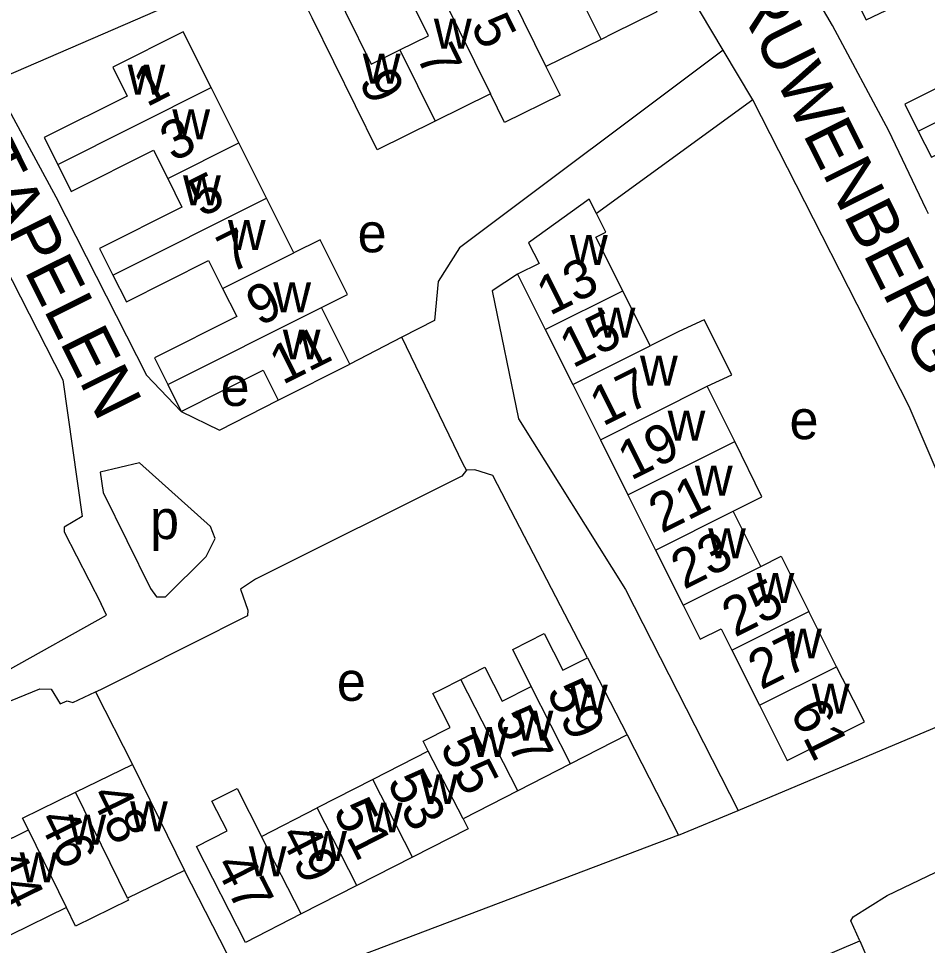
# Model space of a CAD drawing. Extents: x 157794 to 159375, y 380877 to 382306.
# Drawn here: x 158508.3 to 158601.4, y 381608 to 381703 of the extents above; entities that cross this region are included whole.
import ezdxf

# ---------------------------------------------------------------- set-up
doc = ezdxf.new("R2010")
doc.units = 0
for name, color, linetype in [('BLT_Basislijn', 7, 'Continuous'), ('BLT_Bebouwing', 7, 'Continuous'), ('BLT_Centroide', 7, 'Continuous'), ('BLT_Huisnummer', 7, 'Continuous'), ('BLT_Huisnummer_ tussenligend', 7, 'Continuous'), ('BLT_Onderverdeling_panden', 7, 'Continuous'), ('BLT_Straatnaam', 7, 'Continuous')]:
    doc.layers.add(name, color=color, linetype=linetype)

msp = doc.modelspace()

# ---------------------------------------------------------------- linework, layer by layer
at = {"layer": 'BLT_Basislijn'}
for p, q in [((158583.55, 381694.681), (158580.514, 381699.779)), ((158583.55, 381694.681), (158567.509, 381683.019)), ((158550.915, 381672.073), (158547.584, 381670.34)), ((158547.584, 381670.34), (158542.258, 381667.569)), ((158516.19, 381633.988), (158519.958, 381626.542)), ((158570.655, 381629.558), (158575.919, 381619.281)), ((158575.919, 381619.281), (158582.06, 381621.801)), ((158531.991, 381602.592), (158525.289, 381615.669))]:
    msp.add_line(p, q, dxfattribs=at)
for points in [[(158601.545, 381682.996), (158601.318, 381683.475), (158597.468, 381691.525), (158591.727, 381702.299), (158577.351, 381726.851), (158576.73, 381728.832)], [(158580.514, 381699.779), (158567.92, 381720.901), (158565.412, 381723.975), (158562.707, 381724.293), (158532.479, 381708.173), (158505.686, 381696.559)], [(158580.514, 381699.779), (158553.48, 381679.522), (158551.284, 381676.054), (158550.915, 381672.073)], [(158505.686, 381696.559), (158512.107, 381684.735), (158521.411, 381666.438), (158524.963, 381662.744)], [(158582.06, 381621.801), (158607.828, 381632.696), (158609.96, 381635.401), (158610.119, 381638.583), (158599.561, 381663.256), (158583.55, 381694.681)], [(158501.549, 381688.01), (158512.827, 381665.98)], [(158559.431, 381676.796), (158556.821, 381675.112), (158559.525, 381661.971), (158570.503, 381644.47), (158582.06, 381621.801)], [(158554.212, 381656.726), (158553.862, 381657.312), (158547.584, 381670.34)], [(158512.827, 381665.98), (158514.818, 381651.947), (158512.954, 381650.853), (158512.986, 381650.407), (158516.759, 381643)], [(158524.963, 381662.744), (158528.876, 381660.81), (158534.914, 381663.885)], [(158522.438, 381643.727), (158523.37, 381643.713), (158527.516, 381647.862), (158528.438, 381649.706), (158527.977, 381650.935), (158520.685, 381657.466), (158516.645, 381656.513), (158516.962, 381654.425), (158521.829, 381644.575), (158522.438, 381643.727)], [(158554.212, 381656.726), (158553.715, 381656.109), (158532.568, 381645.526), (158531.047, 381644.52), (158531.791, 381642.369), (158531.747, 381641.765), (158520.349, 381636.037)], [(158566.6, 381637.486), (158556.916, 381656.167), (158555.064, 381656.758), (158554.212, 381656.726)], [(158507.165, 381636.164), (158517.292, 381641.844), (158516.759, 381643)], [(158516.19, 381633.988), (158516.721, 381634.236), (158520.349, 381636.037)], [(158487.958, 381625.085), (158510.459, 381634.287), (158511.636, 381634.274), (158512.559, 381632.747), (158513.272, 381633.059), (158513.858, 381632.9), (158516.19, 381633.988)], [(158575.919, 381619.281), (158532.759, 381602.919), (158531.991, 381602.592)], [(158594.52, 381608.439), (158593.573, 381610.486), (158593.827, 381610.899), (158597.328, 381613.114), (158603.952, 381616.296), (158611.163, 381619.281)]]:
    msp.add_lwpolyline(points, dxfattribs=at)
at = {"layer": 'BLT_Bebouwing'}
for p, q in [((158567.994, 381700.882), (158562.344, 381698.092)), ((158530.872, 381690.264), (158528.023, 381695.943)), ((158556.665, 381695.288), (158550.994, 381692.488)), ((158533.711, 381684.605), (158530.872, 381690.264)), ((158536.523, 381679.001), (158533.711, 381684.605)), ((158559.431, 381676.796), (158562.261, 381671.141)), ((158573.037, 381669.464), (158570.207, 381675.119)), ((158542.258, 381667.569), (158539.339, 381673.388)), ((158562.261, 381671.141), (158565.091, 381665.487)), ((158534.914, 381663.885), (158542.258, 381667.569)), ((158523.588, 381665.485), (158524.963, 381662.744)), ((158565.091, 381665.487), (158567.921, 381659.832)), ((158581.694, 381659.655), (158578.863, 381665.31)), ((158567.921, 381659.832), (158570.751, 381654.178)), ((158570.751, 381654.178), (158573.581, 381648.523)), ((158584.359, 381646.844), (158581.528, 381652.5)), ((158592.138, 381636.561), (158589.301, 381642.229)), ((158581.39, 381638.27), (158584.226, 381632.602)), ((158566.6, 381637.486), (158570.655, 381629.558)), ((158570.655, 381629.558), (158564.873, 381626.601)), ((158550.289, 381627.912), (158544.591, 381624.998)), ((158564.873, 381626.601), (158559.448, 381623.826)), ((158514.142, 381623.69), (158519.958, 381626.542)), ((158519.958, 381626.542), (158525.289, 381615.669)), ((158544.591, 381624.998), (158538.891, 381622.083)), ((158559.448, 381623.826), (158553.844, 381620.96)), ((158533.192, 381619.167), (158538.891, 381622.083)), ((158503.603, 381617.01), (158509.304, 381619.824)), ((158548.663, 381617.037), (158542.963, 381614.122)), ((158525.289, 381615.669), (158519.471, 381612.817)), ((158542.963, 381614.122), (158537.263, 381611.207)), ((158513.2, 381611.876), (158507.492, 381609.076))]:
    msp.add_line(p, q, dxfattribs=at)
for points in [[(158559.083, 381718.926), (158561.788, 381720.262), (158567.067, 381709.57), (158570.063, 381711.049), (158573.693, 381703.695), (158569.21, 381701.482), (158567.994, 381700.882)], [(158547.382, 381699.804), (158550.317, 381701.253), (158545.041, 381711.938), (158547.777, 381713.289)], [(158602.941, 381713.681), (158604.311, 381710.947), (158598.92, 381708.245), (158593.76, 381705.618), (158595.156, 381702.878), (158600.552, 381705.485)], [(158550.994, 381692.488), (158545.057, 381689.557), (158538.377, 381703.083), (158536.163, 381707.566), (158539.167, 381709.049), (158544.448, 381698.355), (158547.382, 381699.804)], [(158528.023, 381695.943), (158525.155, 381701.66), (158517.943, 381698.042), (158519.429, 381695.079), (158510.93, 381690.816), (158512.313, 381688.06)], [(158608.57, 381702.364), (158609.934, 381699.642), (158599.136, 381694.227), (158600.507, 381691.491)], [(158600.507, 381691.491), (158601.855, 381688.803), (158612.655, 381694.158), (158614.258, 381690.961), (158618.728, 381693.202), (158624.666, 381696.178), (158621.69, 381702.112), (158618.642, 381700.584)], [(158562.344, 381698.092), (158563.787, 381695.169), (158558.108, 381692.365), (158556.665, 381695.288)], [(158512.313, 381688.06), (158513.695, 381685.305), (158522.112, 381689.527), (158523.578, 381686.604)], [(158523.578, 381686.604), (158525.045, 381683.681), (158516.602, 381679.446), (158517.974, 381676.711)], [(158567.509, 381683.019), (158566.772, 381684.491), (158560.569, 381680.026), (158561.634, 381677.898), (158559.431, 381676.796)], [(158570.207, 381675.119), (158567.461, 381680.606), (158568.465, 381681.109), (158567.509, 381683.019)], [(158539.339, 381673.388), (158542.02, 381674.733), (158539.204, 381680.346), (158536.523, 381679.001)], [(158517.974, 381676.711), (158519.345, 381673.977), (158527.769, 381678.203), (158529.21, 381675.331)], [(158529.21, 381675.331), (158530.65, 381672.46), (158522.212, 381668.227), (158523.588, 381665.485)], [(158578.863, 381665.31), (158581.38, 381666.502), (158578.56, 381672.135), (158575.952, 381670.923), (158573.037, 381669.464)], [(158524.963, 381662.744), (158533.371, 381666.962), (158534.914, 381663.885)], [(158581.528, 381652.5), (158584.479, 381653.977), (158581.694, 381659.655)], [(158573.581, 381648.523), (158576.412, 381642.867)], [(158584.359, 381646.844), (158586.464, 381647.897), (158589.301, 381642.229)], [(158576.412, 381642.867), (158578.158, 381639.38), (158580.298, 381640.451), (158581.39, 381638.27)], [(158560.818, 381634.528), (158558.963, 381638.319), (158562.15, 381639.95), (158564.072, 381636.193), (158566.6, 381637.486)], [(158553.605, 381635.251), (158556.07, 381636.513), (158557.859, 381633.015), (158560.818, 381634.528)], [(158584.226, 381632.602), (158587.063, 381626.934), (158594.975, 381630.893), (158592.737, 381635.364), (158592.138, 381636.561)], [(158550.289, 381627.912), (158549.769, 381628.928), (158552.534, 381630.343), (158550.766, 381633.8), (158551.619, 381634.236), (158553.605, 381635.251)], [(158537.263, 381611.207), (158531.563, 381608.292), (158526.533, 381618.131), (158529.659, 381619.729), (158528.112, 381622.757), (158530.684, 381624.072), (158533.192, 381619.167)], [(158509.304, 381619.824), (158508.714, 381621.028), (158514.142, 381623.69)], [(158553.844, 381620.96), (158554.36, 381619.951), (158548.663, 381617.037)], [(158519.471, 381612.817), (158519.567, 381612.623), (158514.139, 381609.961), (158513.2, 381611.876)], [(158586.996, 381598.939), (158584.727, 381604.272), (158594.52, 381608.439)], [(158594.52, 381608.439), (158596.477, 381603.839), (158596.789, 381603.106)]]:
    msp.add_lwpolyline(points, dxfattribs=at)
at = {"layer": 'BLT_Onderverdeling_panden'}
for p, q in [((158559.083, 381718.926), (158567.994, 381700.882)), ((158547.777, 381713.289), (158556.665, 381695.288)), ((158558.738, 381705.397), (158562.344, 381698.092)), ((158547.382, 381699.804), (158550.994, 381692.488)), ((158600.507, 381691.491), (158618.642, 381700.584)), ((158512.313, 381688.06), (158528.023, 381695.943)), ((158523.578, 381686.604), (158530.872, 381690.264)), ((158517.974, 381676.711), (158533.711, 381684.605)), ((158529.21, 381675.331), (158536.523, 381679.001)), ((158562.261, 381671.141), (158570.207, 381675.119)), ((158523.588, 381665.485), (158539.339, 381673.388)), ((158565.091, 381665.487), (158573.037, 381669.464)), ((158567.921, 381659.832), (158578.863, 381665.31)), ((158570.751, 381654.178), (158581.694, 381659.655)), ((158573.581, 381648.523), (158581.528, 381652.5)), ((158576.412, 381642.867), (158584.359, 381646.844)), ((158581.39, 381638.27), (158589.301, 381642.229)), ((158584.226, 381632.602), (158592.138, 381636.561)), ((158559.448, 381623.826), (158553.605, 381635.251)), ((158564.873, 381626.601), (158560.818, 381634.528)), ((158553.844, 381620.96), (158550.289, 381627.912)), ((158548.663, 381617.037), (158544.591, 381624.998)), ((158519.471, 381612.817), (158514.142, 381623.69)), ((158542.963, 381614.122), (158538.891, 381622.083)), ((158513.2, 381611.876), (158509.304, 381619.824)), ((158537.263, 381611.207), (158533.192, 381619.167))]:
    msp.add_line(p, q, dxfattribs=at)

# ---------------------------------------------------------------- texts
at = {"layer": 'BLT_Centroide'}
for s, p in [('w', (158550.859, 381699.922)), ('w', (158543.578, 381696.344)), ('w', (158519.469, 381695.234)), ('w', (158524.055, 381690.625)), ('w', (158525.156, 381683.859)), ('w', (158529.75, 381679.281)), ('e', (158543.041, 381679.054)), ('w', (158564.812, 381677.75)), ('w', (158534.406, 381672.906)), ('w', (158567.648, 381670.312)), ('w', (158535.375, 381668.062)), ('w', (158571.984, 381665.375)), ('e', (158528.996, 381663.299)), ('w', (158574.812, 381659.75)), ('e', (158587.305, 381659.892)), ('w', (158577.609, 381654.094)), ('p', (158521.774, 381649.648)), ('w', (158578.969, 381647.688)), ('w', (158583.93, 381643.094)), ('w', (158586.758, 381637.406)), ('e', (158540.913, 381633.065)), ('w', (158564.812, 381631.641)), ('w', (158589.602, 381631.75)), ('w', (158559.234, 381628.984)), ('w', (158554.609, 381627.312)), ('w', (158549.469, 381622.469)), ('w', (158519.719, 381619.688)), ('w', (158543.781, 381619.562)), ('w', (158513.406, 381618.312)), ('w', (158538.078, 381616.641)), ('w', (158531.891, 381615.078)), ('w', (158508.406, 381614.453))]:
    msp.add_text(s, height=4, dxfattribs=at).set_placement(p)
at = {"layer": 'BLT_Huisnummer'}
for s, rotation, p in [('5', 296.28239, (158554.588, 381702.291)), ('1', 26.64523, (158521.417, 381693.904)), ('9', 296.28239, (158543.119, 381696.621)), ('5', 26.64523, (158527.06, 381682.596)), ('13', 26.58813, (158562.727, 381672.512)), ('11', 26.64523, (158535.353, 381665.429)), ('17', 26.58813, (158568.173, 381661.17)), ('21', 26.58813, (158574.199, 381650.187)), ('27', 26.58813, (158584.385, 381634.136)), ('59', 297.07752, (158562.344, 381633.994)), ('61', 296.58661, (158587.293, 381632.011)), ('55', 297.07752, (158551.421, 381628.371)), ('48', 296.09974, (158515.588, 381623.408)), ('51', 297.07752, (158540.473, 381621.794)), ('47', 297.07752, (158528.32, 381616.235))]:
    msp.add_text(s, height=4, rotation=rotation, dxfattribs=at).set_placement(p)
at = {"layer": 'BLT_Huisnummer_ tussenligend'}
for s, rotation, p in [('7', 296.28239, (158549, 381699.182)), ('3', 26.64523, (158524.134, 381688.281)), ('7', 26.64523, (158530.003, 381676.84)), ('9', 26.64523, (158532.965, 381671.422)), ('15', 26.58813, (158565.085, 381667.118)), ('19', 26.58813, (158571.043, 381655.612)), ('23', 26.58813, (158576.492, 381644.425)), ('25', 26.58813, (158581.712, 381639.537)), ('57', 297.07752, (158556.997, 381631.234)), ('53', 297.07752, (158546.005, 381624.726)), ('46', 296.09974, (158510.234, 381620.895)), ('49', 297.07752, (158534.973, 381619.292)), ('44', 296.09974, (158504.874, 381616.74))]:
    msp.add_text(s, height=4, rotation=rotation, dxfattribs=at).set_placement(p)
at = {"layer": 'BLT_Straatnaam'}
for s, rotation, p in [('RUWENBERG', 296.63372, (158581.468, 381705.457)), ('STAPELEN', 296.45209, (158501.055, 381692.811))]:
    msp.add_text(s, height=5, rotation=rotation, dxfattribs=at).set_placement(p)

doc.saveas('drawing.dxf')
